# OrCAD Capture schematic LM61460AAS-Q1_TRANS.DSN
size D; title: LM61460-Q1 Automotive 3-V to 36-V, 6-A,; rev: 1.0; note: Datasheet: SNVSB70D      EVM:SNVU621C; note: Synchronous Step Down Converter; note: Low EMI Synchronous Step-Down Converter
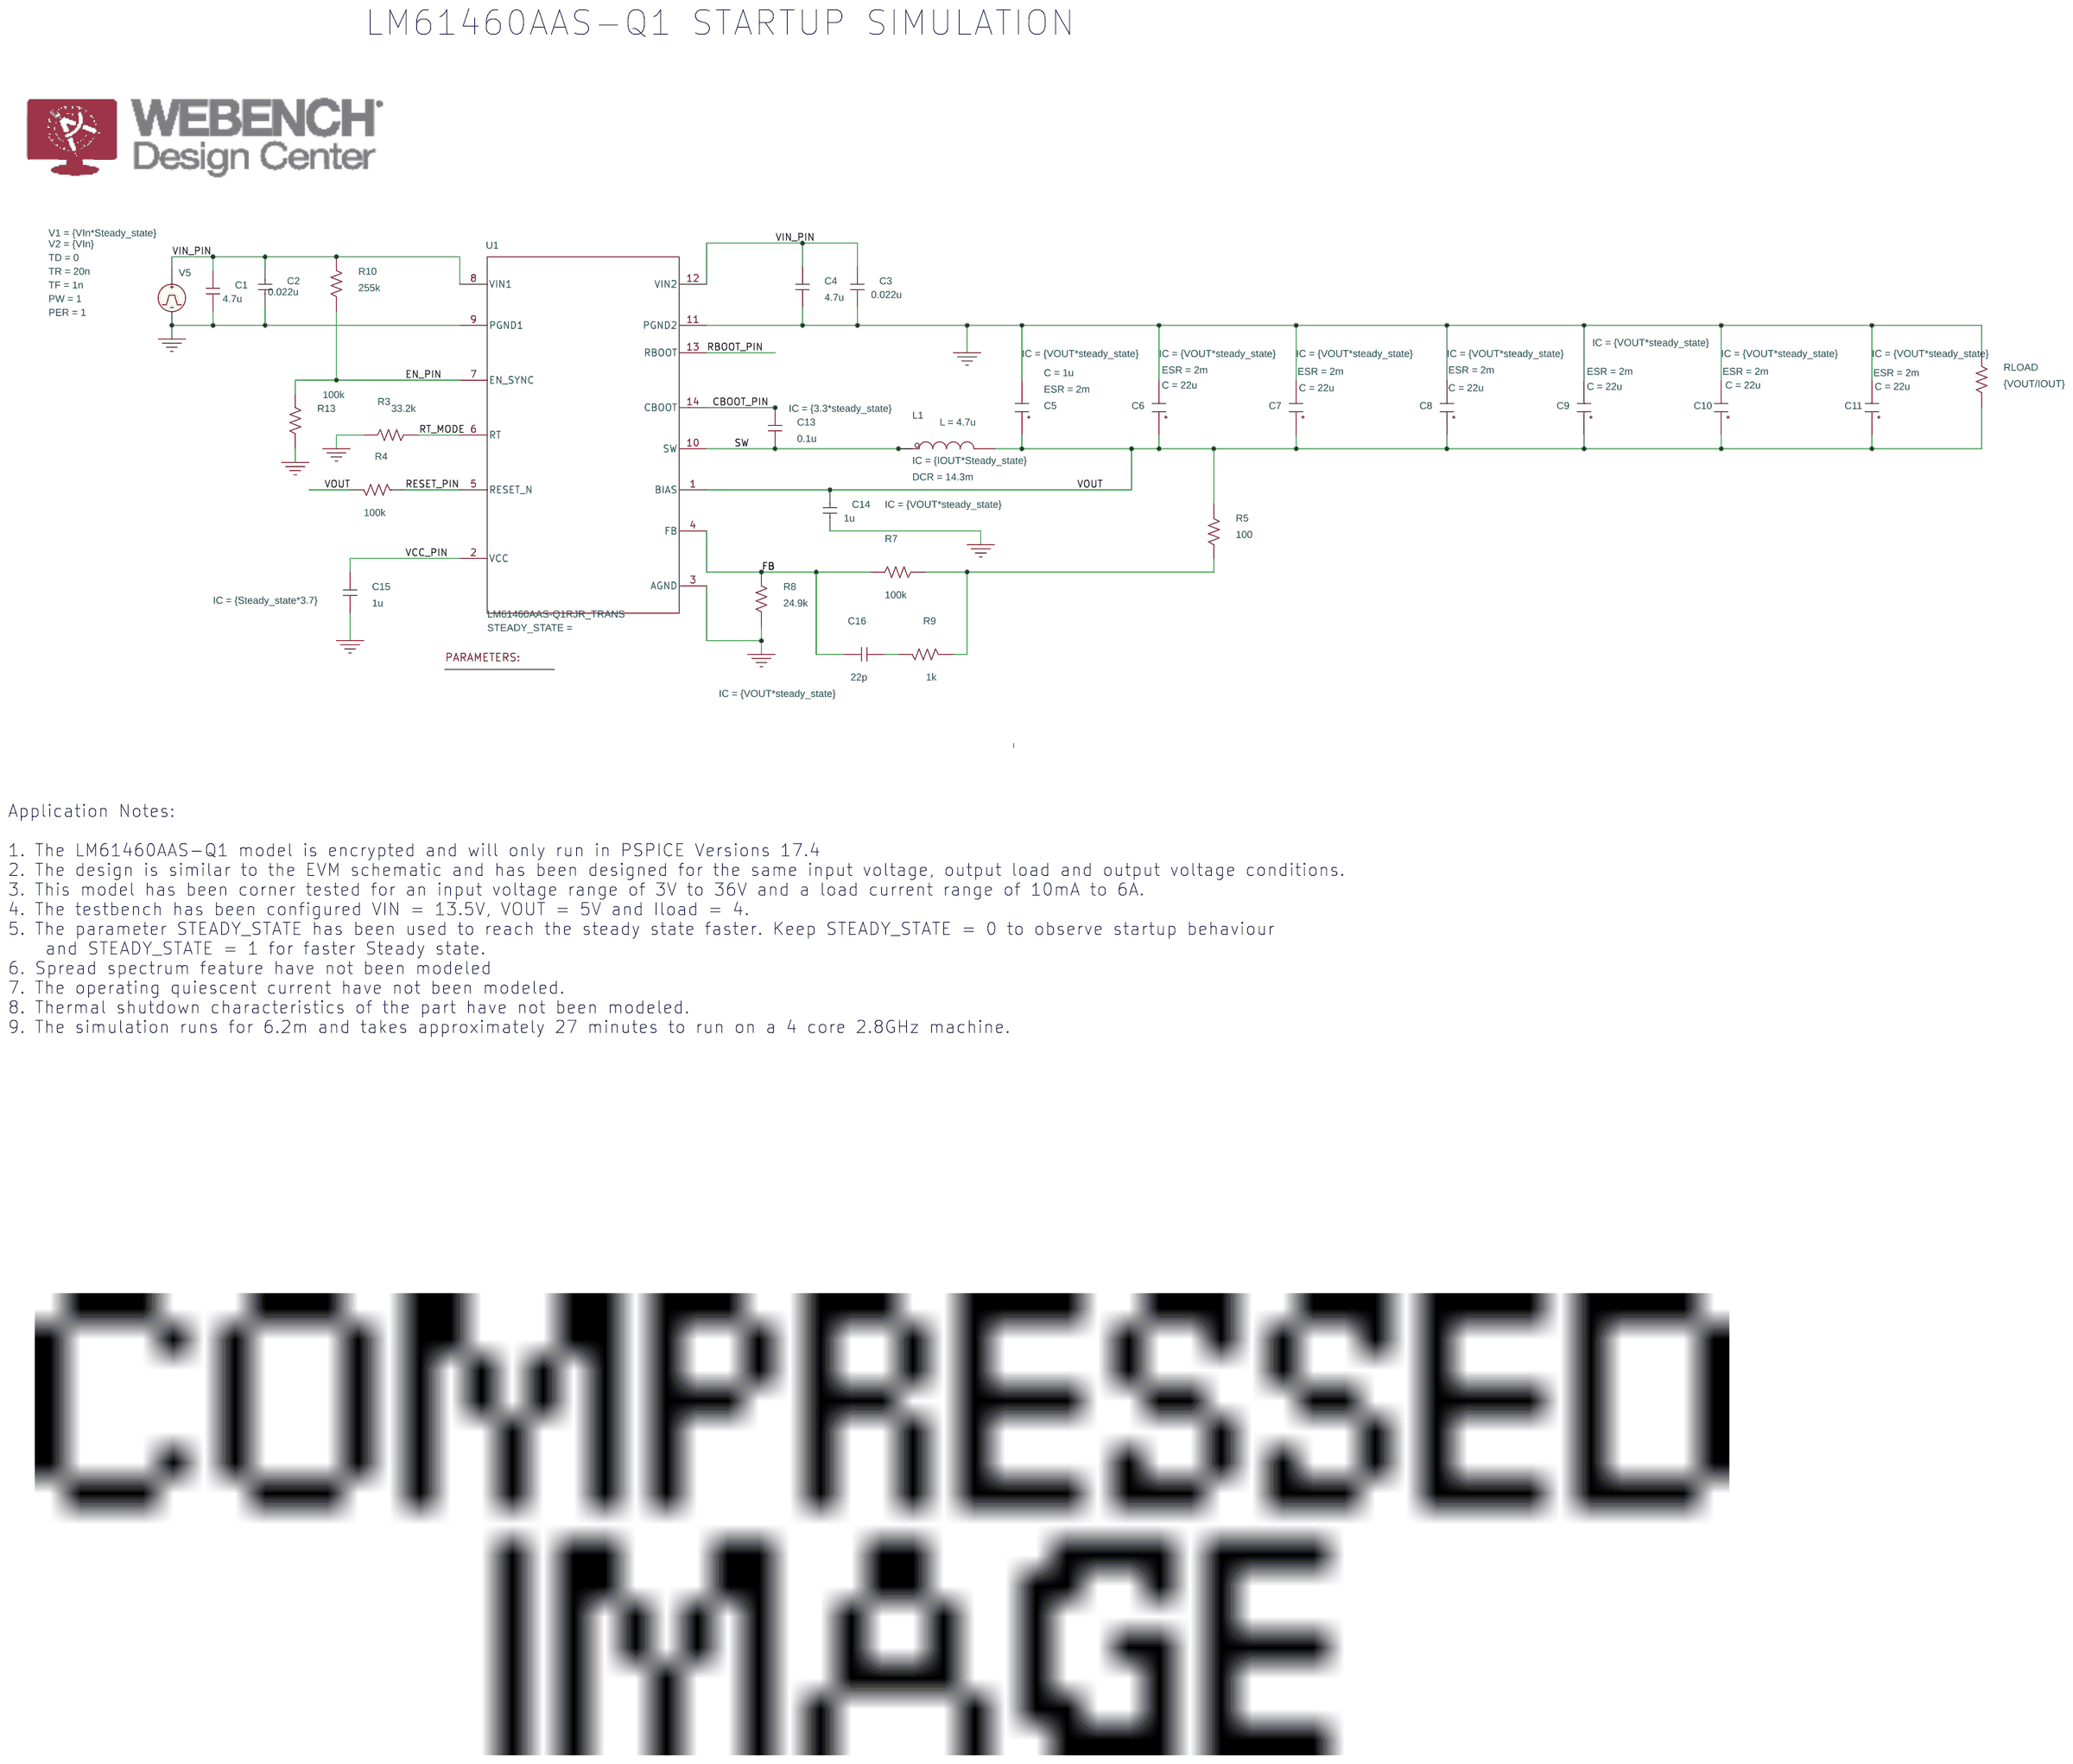
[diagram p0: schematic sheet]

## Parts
1  PARAM
C1  4.7u  [RAD/CK05]
C2  0.022u  [RAD/CK05]
C3  0.022u  [RAD/CK05]
C4  4.7u  [RAD/CK05]
C5  CESR
C6  CESR
C7  CESR
C8  CESR
C9  CESR
C10  CESR
C11  CESR
C13  0.1u  [RAD/CK05]
C14  1u  [RAD/CK05]
C15  1u  [RAD/CK05]
C16  22p  [RAD/CK05]
L1  LDCR
R3  33.2k  [AX/RC05]
R4  100k  [AX/RC05]
R5  100  [AX/RC05]
R7  100k  [AX/RC05]
R8  24.9k  [AX/RC05]
R9  1k  [AX/RC05]
R10  255k  [AX/RC05]
R13  100k  [AX/RC05]
RLOAD  {VOUT/IOUT}  [AX/RC05]
U1  LM61460AAS-Q1RJR_TRANS  [RJR0014A]
V5  VPULSE

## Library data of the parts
1 = PARAM: Iout: 4; Steady_state: 0; VIn: 13.5; Vout: 5
C1-C4 = C
C5 = CESR_0: C: 1u; ESR: 2m; IC: {VOUT*steady_state}; PSpiceTemplate: X^@REFDES %IN %OUT @MODEL PARAMS:  ?C|C=@C||C=100u|  ?ESR|ESR=@ESR||ESR=0.01| ?X|X=@X||X=2|  ?IC|IC=@IC||IC=2|; X: 1
C6-C11 = CESR_0: C: 22u; ESR: 2m; IC: {VOUT*steady_state}; PSpiceTemplate: X^@REFDES %IN %OUT @MODEL PARAMS:  ?C|C=@C||C=100u|  ?ESR|ESR=@ESR||ESR=0.01| ?X|X=@X||X=2|  ?IC|IC=@IC||IC=2|; X: 1
C13 = C: IC: {3.3*steady_state}
C14 C16 = C: IC: {VOUT*steady_state}
C15 = C: IC: {Steady_state*3.7}
L1 = LDCR_0: DCR: 14.3m; IC: {IOUT*Steady_state}; L: 4.7u; PSpiceTemplate: X^@REFDES %IN %OUT @MODEL PARAMS:  ?L|L=@L||L=1u|  ?DCR|DCR=@DCR||DCR=0.01| ?IC|IC=@IC||IC=0|
R3-R5 R7-R10 R13 RLOAD = R
U1 = LM61460AAS-Q1RJR_TRANS
V5 = VPULSE: PER: 1; PW: 1; TD: 0; TF: 1n; TR: 20n; V1: {VIn*Steady_state}; V2: {VIn}

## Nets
VCC_PIN: C15.1 U1.2(VCC)
VIN_PIN: C1.1 C2.1 C3.1 C4.1 R10.2 U1.8(VIN1) U1.12(VIN2) V5.1(+)
0: C1.2 C2.2 C3.2 C4.2 C5.2(OUT) C6.2(OUT) C7.2(OUT) C8.2(OUT) C9.2(OUT) C10.2(OUT) C11.2(OUT) C14.2 C15.2 R3.2 R8.1 R13.1 RLOAD.2 U1.3(AGND) U1.9(PGND1) U1.11(PGND2) V5.2(-)
CBOOT_PIN: C13.1 U1.14(CBOOT)
EN_PIN: R10.1 R13.2 U1.7(EN_SYNC)
FB: C16.2 R7.2 R8.2 U1.4(FB)
RBOOT_PIN: U1.13(RBOOT)
RESET_PIN: R4.1 U1.5(RESET_N)
RT_MODE: R3.1 U1.6(RT)
SW: C13.2 L1.1(IN) U1.10(SW)
VOUT: C5.1(IN) C6.1(IN) C7.1(IN) C8.1(IN) C9.1(IN) C10.1(IN) C11.1(IN) C14.1 L1.3(OUT) R4.2 R5.1 RLOAD.1 U1.1(BIAS)
N16785504: C16.1 R9.2
N16785516: R5.2 R7.1 R9.1

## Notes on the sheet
- LM61460AAS-Q1 STARTUP SIMULATION
- Application Notes:
  1. The LM61460AAS-Q1 model is encrypted and will only run in PSPICE Versions 17.4
  2. The design is similar to the EVM schematic and has been designed for the same input voltage, output load and output voltage conditions.
  3. This model has been corner tested for an input voltage range of 3V to 36V and a load current range of 10mA to 6A.
  4. The testbench has been configured VIN = 13.5V, VOUT = 5V and Iload = 4.
  5. The parameter STEADY_STATE has been used to reach the steady state faster. Keep STEADY_STATE = 0 to observe startup behaviour
      and STEADY_STATE = 1 for faster Steady state.
  6. Spread spectrum feature have not been modeled
  7. The operating quiescent current have not been modeled.
  8. Thermal shutdown characteristics of the part have not been modeled.
  9. The simulation runs for 6.2m and takes approximately 27 minutes to run on a 4 core 2.8GHz machine.
